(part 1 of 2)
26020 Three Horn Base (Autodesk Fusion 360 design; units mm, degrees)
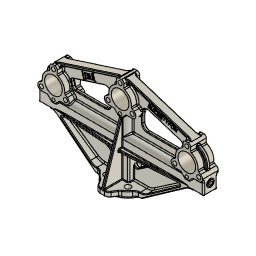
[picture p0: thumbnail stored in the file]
parameter "Bell_Tolerance" = 0.1984 (= "( 1 / 128 ) * 1 in")
parameter "Bolt_Hole_Tolerance" = 0.7937 (= "( 1 / 32 ) * 1 in")
parameter "Dowel_Hole_Tolerance" = 0.0992 (= "( 1 / 256 ) * 1 in")
sketch "Layout Profile" plane through (0, 0, 0) normal (0, 1, 0) x axis (1, 0, 0)
  line L1 (50.8, 0) -> (-50.8, 0)
  line L2 (0, -190.5) -> (0, 0)
  line L3 (168.275, -136.525) -> (-168.275, -136.525)
  line L4 (-110.7733, -12.7) -> (-225.7767, -12.7)
  circle C1 centre (0, -190.5) radius 80.9625
  arc A1 centre (-168.275, -136.525) radius 136.525 clockwise from (-110.7733, -12.7) to (-225.7767, -12.7)
  circle C2 centre (168.275, -136.525) radius 114.3
  point P4 (0, 0)
  point P1 (0, 0)
  point P5 (0, 0)
  point P6 (0, -190.5)
  point P7 (0, -190.5)
  point P10 (0, -136.525)
  point P8 (-168.275, -136.525)
  point P11 (-168.275, -136.525)
  point P9 (168.275, -136.525)
  point P14 (168.275, -136.525)
  point P2 (-50.8, 0)
  point P3 (50.8, 0)
  horizontal L1
  midpoint L1 P4
  coincident P1 P4
  coincident P1 P5
  perpendicular L1 L2
  coincident P6 P7
  horizontal L3
  midpoint L3 P10
  coincident L2 P10
  coincident P8 P11
  horizontal L4
  coincident P9 P14
  dimension "d1" distance P2 P3 = 101.6
  dimension "d2" diameter C1 = 161.925 (= "6 3/8")
  dimension "d3" distance L2 P8 = 168.275 (= "6 5/8")
  dimension "d4" distance L1 L3 = 136.525 (= "5 3/8")
  dimension "d5" distance P7 L3 = 53.975 (= "2 1/8")
  dimension "d6" diameter A1 = 273.05 (= "10 3/4")
  dimension "d7" distance L1 L4 = 12.7 (= "( 1 / 2 ) * 1 in")
  dimension "d8" diameter C2 = 228.6
sketch "Main Profile" plane through (0, 0, 0) normal (0, 1, 0) x axis (1, 0, 0)
  line L1 (50.8, 0) -> (-50.8, 0)
  line L2 (51.5937, -3.175) -> (50.8, 0)
  line L3 (57.15, -3.175) -> (51.5937, -3.175)
  line L4 (168.275, 0) -> (50.8, 0)
  line L5 (168.275, -136.525) -> (168.275, 0)
  line L6 (0, -190.5) -> (0, 0)
  line L7 (64.4424, -15.875) -> (0, -15.875)
  line L8 (157.0466, -79.375) -> (64.4424, -15.875)
  line L9 (168.275, -79.375) -> (57.15, -3.175)
  line L10 (168.275, -180.975) -> (168.275, -136.525)
  line L11 (171.45, -180.975) -> (165.1, -180.975)
  line L12 (177.8, -165.6244) -> (177.8, -174.625)
  line L13 (198.5209, -119.0625) -> (168.275, -136.525)
  line L14 (138.0291, -119.0625) -> (168.275, -136.525)
  line L15 (203.2834, -127.3114) -> (198.2383, -130.2242)
  line L16 (198.5209, -109.5375) -> (183.3562, -109.5375)
  line L17 (172.2438, -98.425) -> (164.3062, -98.425)
  line L18 (183.3562, -109.5375) -> (172.2438, -98.425)
  line L19 (153.1938, -109.5375) -> (164.3062, -98.425)
  line L20 (138.0291, -109.5375) -> (153.1938, -109.5375)
  line L21 (133.2666, -127.3114) -> (138.3117, -130.2242)
  line L22 (158.75, -165.6244) -> (158.75, -174.625)
  line L23 (0, -234.95) -> (0, -190.5)
  line L24 (3.175, -234.95) -> (-3.175, -234.95)
  line L25 (9.525, -219.5994) -> (9.525, -228.6)
  line L26 (30.2459, -163.5125) -> (15.0813, -163.5125)
  line L27 (29.9633, -184.1992) -> (35.0084, -181.2864)
  line L28 (3.9688, -152.4) -> (-3.9687, -152.4)
  line L29 (15.0813, -163.5125) -> (3.9688, -152.4)
  line L30 (-15.0812, -163.5125) -> (-3.9687, -152.4)
  line L31 (-30.2459, -163.5125) -> (-15.0812, -163.5125)
  line L32 (-29.9633, -184.1992) -> (-35.0084, -181.2864)
  line L33 (-9.525, -219.5994) -> (-9.525, -228.6)
  line L34 (-138.0291, -119.0625) -> (-168.275, -136.525)
  line L35 (-138.0291, -109.5375) -> (-153.1938, -109.5375)
  line L36 (-153.1938, -109.5375) -> (-164.3062, -98.425)
  line L37 (-172.2438, -98.425) -> (-164.3062, -98.425)
  line L38 (-183.3562, -109.5375) -> (-172.2438, -98.425)
  line L39 (-198.5209, -109.5375) -> (-183.3562, -109.5375)
  line L40 (-203.2834, -127.3114) -> (-198.2383, -130.2242)
  line L41 (-198.5209, -119.0625) -> (-168.275, -136.525)
  line L42 (-168.275, -180.975) -> (-168.275, -136.525)
  line L43 (-177.8, -165.6244) -> (-177.8, -174.625)
  line L44 (-171.45, -180.975) -> (-165.1, -180.975)
  line L45 (-158.75, -165.6244) -> (-158.75, -174.625)
  line L46 (-133.2666, -127.3114) -> (-138.3117, -130.2242)
  line L47 (-168.275, -136.525) -> (-168.275, 0)
  line L48 (-168.275, 0) -> (-50.8, 0)
  line L49 (173.3895, -180.6716) -> (5.1145, -234.6466)
  line L50 (159.9347, -178.3186) -> (9.525, -226.5632)
  line L51 (135.9945, -159.3229) -> (56.3499, -184.8693)
  line L52 (39.7709, -149.225) -> (39.7709, -172.7761)
  line L53 (52.4709, -136.525) -> (130.7079, -136.525)
  line L54 (130.7079, -136.525) -> (168.275, -136.525)
  line L55 (208.0459, -79.375) -> (208.0459, -119.0625)
  line L56 (0, -79.375) -> (208.0459, -79.375)
  line L57 (128.6373, -117.475) -> (17.4625, -117.475)
  line L58 (168.275, -85.725) -> (168.275, -79.375)
  line L59 (0, -85.725) -> (168.275, -85.725)
  line L60 (17.4625, -163.5125) -> (17.4625, -117.475)
  line L61 (3.175, -49.5697) -> (3.175, -15.875)
  line L62 (3.175, -152.4) -> (3.175, -77.4303)
  line L63 (3.175, -77.4303) -> (3.175, -49.5697)
  line L64 (19.05, -15.875) -> (19.05, -79.375)
  line L65 (14.2875, -79.375) -> (14.2875, -63.5)
  line L66 (61.5498, -67.788) -> (28.9911, -45.462)
  line L67 (-61.5498, -67.788) -> (-28.9911, -45.462)
  line L68 (0, -79.375) -> (-208.0459, -79.375)
  line L69 (-19.05, -15.875) -> (-19.05, -79.375)
  line L70 (-14.2875, -79.375) -> (-14.2875, -63.5)
  line L71 (-3.175, -77.4303) -> (-3.175, -49.5697)
  line L72 (-3.175, -152.4) -> (-3.175, -77.4303)
  line L73 (0, -85.725) -> (-168.275, -85.725)
  line L74 (-3.175, -49.5697) -> (-3.175, -15.875)
  line L75 (-157.0466, -79.375) -> (-64.4424, -15.875)
  line L76 (-64.4424, -15.875) -> (0, -15.875)
  line L77 (-51.5937, -3.175) -> (-50.8, 0)
  line L78 (-57.15, -3.175) -> (-51.5937, -3.175)
  line L79 (-168.275, -79.375) -> (-57.15, -3.175)
  line L80 (-168.275, -85.725) -> (-168.275, -79.375)
  line L81 (-17.4625, -163.5125) -> (-17.4625, -117.475)
  line L82 (-128.6373, -117.475) -> (-17.4625, -117.475)
  line L83 (-39.7709, -149.225) -> (-39.7709, -172.7761)
  line L84 (-135.9945, -159.3229) -> (-56.3499, -184.8693)
  line L85 (-52.4709, -136.525) -> (-130.7079, -136.525)
  line L86 (-130.7079, -136.525) -> (-168.275, -136.525)
  line L87 (-159.9347, -178.3186) -> (-9.525, -226.5632)
  line L88 (-173.3895, -180.6716) -> (-5.1145, -234.6466)
  line L89 (-208.0459, -79.375) -> (-208.0459, -119.0625)
  line L90 (0, -152.4) -> (0, -15.875)
  line L91 (-17.4625, -117.475) -> (17.4625, -117.475)
  line L92 (0, -3.175) -> (51.5937, -3.175)
  line L93 (0, 0) -> (0, -3.175)
  line L94 (-51.5937, -3.175) -> (0, -3.175)
  circle C1 centre (168.275, -136.525) radius 22.3242
  circle C2 centre (0, -190.5) radius 22.3242
  arc A1 centre (171.45, -174.625) radius 6.35 clockwise from (177.8, -174.625) to (171.45, -180.975)
  circle C3 centre (168.275, -171.45) radius 5.1594
  arc A2 centre (180.975, -165.6244) radius 3.175 clockwise from (177.8, -165.6244) to (179.705, -162.7144)
  arc A3 centre (168.275, -136.525) radius 28.575 clockwise from (196.6707, -133.329) to (179.705, -162.7144)
  circle C4 centre (198.5209, -119.0625) radius 5.1594
  circle C5 centre (138.0291, -119.0625) radius 5.1594
  arc A4 centre (199.8258, -132.9738) radius 3.175 clockwise from (196.6707, -133.329) to (198.2383, -130.2242)
  arc A5 centre (198.5209, -119.0625) radius 9.525 clockwise from (198.5209, -109.5375) to (203.2834, -127.3114)
  circle C6 centre (168.275, -104.775) radius 3.9688
  arc A6 centre (138.0291, -119.0625) radius 9.525 clockwise from (133.2666, -127.3114) to (138.0291, -109.5375)
  arc A7 centre (136.7242, -132.9738) radius 3.175 clockwise from (138.3117, -130.2242) to (139.8793, -133.329)
  arc A8 centre (168.275, -136.525) radius 28.575 clockwise from (156.845, -162.7144) to (139.8793, -133.329)
  arc A9 centre (155.575, -165.6244) radius 3.175 clockwise from (156.845, -162.7144) to (158.75, -165.6244)
  arc A10 centre (165.1, -174.625) radius 6.35 clockwise from (165.1, -180.975) to (158.75, -174.625)
  arc A11 centre (3.175, -228.6) radius 6.35 clockwise from (9.525, -228.6) to (3.175, -234.95)
  circle C7 centre (0, -225.425) radius 5.1594
  arc A12 centre (12.7, -219.5994) radius 3.175 clockwise from (9.525, -219.5994) to (11.43, -216.6894)
  arc A13 centre (0, -190.5) radius 28.575 clockwise from (28.3957, -187.304) to (11.43, -216.6894)
  circle C8 centre (30.2459, -173.0375) radius 5.1594
  circle C9 centre (-30.2459, -173.0375) radius 5.1594
  arc A14 centre (30.2459, -173.0375) radius 9.525 clockwise from (30.2459, -163.5125) to (35.0084, -181.2864)
  arc A15 centre (31.5508, -186.9488) radius 3.175 clockwise from (28.3957, -187.304) to (29.9633, -184.1992)
  circle C10 centre (0, -158.75) radius 3.9687
  arc A16 centre (-30.2459, -173.0375) radius 9.525 clockwise from (-35.0084, -181.2864) to (-30.2459, -163.5125)
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  point P4 (0, 0)
  point P1 (0, 0)
  point P8 (168.275, -136.525)
  point P9 (168.275, -136.525)
  point P10 (0, 0)
  point P11 (0, -190.5)
  point P12 (0, -190.5)
  point P15 (0, -190.5)
  point P14 (168.275, -136.525)
  point P16 (0, -15.875)
  point P17 (0, -15.875)
  point P21 (168.275, -136.525)
  point P25 (168.275, -180.975)
  point P22 (168.275, -180.975)
  point P29 (168.275, -171.45)
  point P33 (168.275, -136.525)
  point P36 (168.275, -136.525)
  point P34 (198.5209, -119.0625)
  point P37 (198.5209, -119.0625)
  point P38 (168.275, -136.525)
  point P35 (138.0291, -119.0625)
  point P39 (138.0291, -119.0625)
  point P48 (168.275, -98.425)
  point P49 (168.275, -104.775)
  point P24 (171.45, -180.975)
  point P63 (165.1, -180.975)
  point P26 (177.8, -174.625)
  point P64 (158.75, -174.625)
  point P28 (177.8, -165.6244)
  point P61 (158.75, -165.6244)
  point P30 (179.705, -162.7144)
  point P59 (156.845, -162.7144)
  point P32 (196.6707, -133.329)
  point P57 (139.8793, -133.329)
  point P40 (198.2383, -130.2242)
  point P55 (138.3117, -130.2242)
  point P42 (203.2834, -127.3114)
  point P54 (133.2666, -127.3114)
  point P43 (183.3562, -109.5375)
  point P51 (153.1938, -109.5375)
  point P44 (198.5209, -109.5375)
  point P52 (138.0291, -109.5375)
  point P47 (172.2438, -98.425)
  point P50 (164.3062, -98.425)
  point P69 (0, -234.95)
  point P66 (0, -234.95)
  point P65 (0, -190.5)
  point P73 (0, -225.425)
  point P89 (0, -152.4)
  point P80 (15.0813, -163.5125)
  point P81 (15.0813, -163.5125)
  point P90 (0, -158.75)
  point P68 (3.175, -234.95)
  point P106 (-3.175, -234.95)
  point P70 (9.525, -228.6)
  point P104 (-9.525, -228.6)
  point P72 (9.525, -219.5994)
  point P103 (-9.525, -219.5994)
  point P74 (11.43, -216.6894)
  point P101 (-11.43, -216.6894)
  point P76 (28.3957, -187.304)
  point P99 (-28.3957, -187.304)
  point P92 (-15.0812, -163.5125)
  point P93 (-15.0812, -163.5125)
  point P82 (30.2459, -163.5125)
  point P94 (-30.2459, -163.5125)
  point P83 (35.0084, -181.2864)
  point P96 (-35.0084, -181.2864)
  point P85 (29.9633, -184.1992)
  point P97 (-29.9633, -184.1992)
  point P88 (3.9688, -152.4)
  point P91 (-3.9687, -152.4)
  point P3 (50.8, 0)
  point P151 (-50.8, 0)
  point P7 (168.275, 0)
  point P149 (-168.275, 0)
  point P150 (-168.275, -136.525)
  point P128 (-168.275, -136.525)
  point P129 (-168.275, -180.975)
  point P23 (165.1, -180.975)
  point P135 (-165.1, -180.975)
  point P134 (-171.45, -180.975)
  point P132 (-177.8, -174.625)
  point P131 (-177.8, -165.6244)
  point P124 (-179.705, -162.7144)
  point P122 (-196.6707, -133.329)
  point P126 (-168.275, -136.525)
  point P127 (-198.5209, -119.0625)
  point P108 (-168.275, -136.525)
  point P109 (-138.0291, -119.0625)
  point P120 (-198.2383, -130.2242)
  point P119 (-203.2834, -127.3114)
  point P116 (-183.3562, -109.5375)
  point P117 (-198.5209, -109.5375)
  point P46 (164.3062, -98.425)
  point P114 (-164.3062, -98.425)
  point P115 (-172.2438, -98.425)
  point P113 (-164.3062, -98.425)
  point P111 (-153.1938, -109.5375)
  point P112 (-138.0291, -109.5375)
  point P145 (-133.2666, -127.3114)
  point P146 (-138.3117, -130.2242)
  point P141 (-139.8793, -133.329)
  point P142 (-156.845, -162.7144)
  point P139 (-158.75, -165.6244)
  point P138 (-165.1, -180.975)
  point P137 (-158.75, -174.625)
  point P153 (5.1145, -234.6466)
  point P154 (173.3895, -180.6716)
  point P155 (9.525, -226.5632)
  point P156 (159.9347, -178.3186)
  point P170 (168.275, -136.525)
  point P171 (208.0459, -119.0625)
  point P175 (128.6373, -117.475)
  point P20 (168.275, -79.375)
  point P19 (157.0466, -79.375)
  point P176 (168.275, -79.375)
  point P177 (168.275, -85.725)
  point P178 (0, -85.725)
  point P173 (0, -79.375)
  point P180 (3.175, -15.875)
  point P184 (3.175, -152.4)
  point P183 (0, -63.5)
  point P185 (19.05, -79.375)
  point P186 (19.05, -15.875)
  point P188 (14.2875, -79.375)
  point P190 (20.6375, -117.475)
  point P189 (17.4625, -120.65)
  point P192 (19.05, -50.6991)
  point P196 (57.9586, -79.375)
  point P220 (-50.8, 0)
  point P5 (51.5937, -3.175)
  point P221 (-51.5937, -3.175)
  point P6 (57.15, -3.175)
  point P222 (-57.15, -3.175)
  point P219 (0, -15.875)
  point P18 (64.4424, -15.875)
  point P217 (-64.4424, -15.875)
  point P218 (-157.0466, -79.375)
  point P223 (-168.275, -79.375)
  point P247 (-5.1145, -234.6466)
  point P248 (-173.3895, -180.6716)
  point P245 (-9.525, -226.5632)
  point P246 (-159.9347, -178.3186)
  point P157 (56.3499, -184.8693)
  point P236 (-56.3499, -184.8693)
  point P158 (135.9945, -159.3229)
  point P237 (-135.9945, -159.3229)
  point P159 (39.7709, -172.7761)
  point P234 (-39.7709, -172.7761)
  point P161 (39.7709, -149.225)
  point P233 (-39.7709, -149.225)
  point P162 (139.7584, -150.4844)
  point P240 (-139.7584, -150.4844)
  point P164 (136.9691, -141.8167)
  point P242 (-136.9691, -141.8167)
  point P166 (130.7079, -136.525)
  point P238 (-130.7079, -136.525)
  point P168 (52.4709, -136.525)
  point P232 (-52.4709, -136.525)
  point P244 (-168.275, -136.525)
  point P249 (-208.0459, -119.0625)
  point P172 (208.0459, -79.375)
  point P204 (-208.0459, -79.375)
  point P205 (0, -79.375)
  point P174 (17.4625, -117.475)
  point P225 (-17.4625, -117.475)
  point P230 (-128.6373, -117.475)
  point P224 (-168.275, -79.375)
  point P214 (-168.275, -85.725)
  point P215 (0, -85.725)
  point P179 (17.4625, -163.5125)
  point P226 (-17.4625, -163.5125)
  point P216 (-3.175, -15.875)
  point P181 (3.175, -49.5697)
  point P212 (-3.175, -49.5697)
  point P182 (3.175, -77.4303)
  point P211 (-3.175, -77.4303)
  point P213 (-3.175, -152.4)
  point P206 (-19.05, -79.375)
  point P207 (-19.05, -15.875)
  point P187 (14.2875, -63.5)
  point P208 (-14.2875, -63.5)
  point P209 (-14.2875, -79.375)
  point P229 (-17.4625, -120.65)
  point P228 (-20.6375, -117.475)
  point P200 (-19.05, -50.6991)
  point P193 (28.9911, -45.462)
  point P199 (-28.9911, -45.462)
  point P195 (61.5498, -67.788)
  point P201 (-61.5498, -67.788)
  point P203 (-57.9586, -79.375)
  point P250 (0, -152.4)
  point P254 (177.8, -172.446)
  point P256 (203.9245, -126.9064)
  point P251 (179.9167, -169.4526)
  point P259 (-179.9167, -169.4526)
  point P252 (202.6048, -130.1047)
  point P262 (-202.6048, -130.1047)
  point P260 (-177.8, -172.446)
  point P264 (-203.9245, -126.9064)
  point P265 (0, -3.175)
  point P266 (0, 0)
  point P2 (-50.8, 0)
  point P87 (-3.9687, -152.4)
  point P77 (0, -190.5)
  horizontal L1
  midpoint L1 P4
  coincident P1 P4
  horizontal L3
  parallel L1 L4
  perpendicular L4 L5
  coincident P8 P9
  coincident P1 P10
  perpendicular L1 L6
  coincident P11 P12
  coincident P12 P15
  coincident P9 P14
  coincident L6 P16
  coincident P16 P17
  perpendicular L6 L7
  parallel L8 L9
  coincident P9 P21
  parallel L5 L10
  horizontal L11
  midpoint L11 P25
  coincident P22 P25
  tangent L11 A1
  vertical L12
  tangent A1 L12
  coincident L10 P29
  tangent L12 A2
  tangent A2 A3
  concentric C1 A3
  coincident P33 P36
  coincident P34 P37
  coincident P14 P38
  coincident P35 P39
  tangent A3 A4
  tangent A4 L15
  horizontal L16
  tangent L16 A5
  tangent L15 A5
  concentric C4 A5
  perpendicular L5 L17
  midpoint L17 P48
  coincident L5 P48
  coincident L5 P49
  symmetric L10 P24 P63
  symmetric L10 P26 P64
  symmetric L10 A1 A10
  symmetric L10 P28 P61
  symmetric L10 P30 P59
  symmetric L10 A2 A9
  symmetric L10 P32 P57
  symmetric L10 A3 A8
  symmetric L10 P40 P55
  symmetric L10 A4 A7
  symmetric L10 P42 P54
  symmetric L10 P43 P51
  symmetric L10 P44 P52
  symmetric L10 A5 A6
  symmetric L10 P47 P50
  parallel L6 L23
  horizontal L24
  midpoint L24 P69
  coincident P66 P69
  coincident P15 P65
  tangent L24 A11
  tangent A11 L25
  vertical L25
  coincident L23 P73
  tangent L25 A12
  tangent A12 A13
  concentric C2 A13
  tangent L26 A14
  concentric C8 A14
  tangent A14 L27
  tangent L27 A15
  tangent A13 A15
  perpendicular L6 L28
  midpoint L28 P89
  coincident L6 P89
  coincident P80 P81
  horizontal L26
  coincident L6 P90
  symmetric L23 P68 P106
  symmetric L23 P70 P104
  symmetric L23 P72 P103
  symmetric L23 P74 P101
  symmetric L23 P76 P99
  symmetric L23 P80 P92
  symmetric L23 P81 P93
  symmetric L23 P82 P94
  symmetric L23 P83 P96
  symmetric L23 A14 A16
  symmetric L23 P85 P97
  symmetric L23 P88 P91
  symmetric P3 L6 P151
  symmetric P7 L6 P149
  symmetric P8 L6 P150
  symmetric L6 P21 P128
  symmetric L6 P22 P129
  symmetric L6 P23 P135
  symmetric L6 P24 P134
  symmetric L6 P26 P132
  symmetric L6 P28 P131
  symmetric L6 P30 P124
  symmetric L6 P32 P122
  symmetric L6 P36 P126
  symmetric L6 P37 P127
  symmetric L6 P38 P108
  symmetric L6 P39 P109
  symmetric L6 P40 P120
  symmetric L6 P42 P119
  symmetric L6 P43 P116
  symmetric L6 P44 P117
  symmetric L6 P46 P114
  symmetric L6 P47 P115
  symmetric L6 P50 P113
  symmetric L6 P51 P111
  symmetric L6 P52 P112
  symmetric L6 P54 P145
  symmetric L6 P55 P146
  symmetric L6 P57 P141
  symmetric L6 P59 P142
  symmetric L6 P61 P139
  symmetric L6 P63 P138
  symmetric L6 P64 P137
  coincident A11 P153
  tangent A11 L49
  coincident A1 P154
  tangent A1 L49
  parallel L49 L50
  coincident L25 P155
  coincident A10 P156
  parallel L50 L51
  vertical L52
  tangent A14 L52
  horizontal L53
  coincident P14 P170
  horizontal L54
  coincident A5 P171
  vertical L55
  tangent A5 L55
  perpendicular L55 L56
  horizontal L57
  coincident A6 P175
  coincident P20 L56
  coincident L5 P20
  coincident P19 L56
  coincident L5 P176
  coincident L56 P176
  coincident L5 P177
  perpendicular L56 L58
  perpendicular L5 L59
  perpendicular L57 L60
  coincident L6 P178
  coincident L6 P173
  coincident L7 P180
  perpendicular L7 L61
  perpendicular L57 L62
  coincident L28 P184
  coincident L6 P183
  parallel L62 L63
  coincident L56 P185
  coincident L7 P186
  perpendicular L7 L64
  coincident L56 P188
  perpendicular L56 L65
  coincident L57 P190
  coincident L60 P189
  coincident L64 P192
  coincident L56 P196
  parallel L8 L66
  symmetric P3 L6 P220
  symmetric P5 L6 P221
  symmetric P6 L6 P222
  symmetric L6 P17 P219
  symmetric L6 P18 P217
  symmetric L6 P19 P218
  symmetric L6 P20 P223
  symmetric L6 P153 P247
  symmetric L6 P154 P248
  symmetric L6 P155 P245
  symmetric L6 P156 P246
  symmetric L6 P157 P236
  symmetric L6 P158 P237
  symmetric L6 P159 P234
  symmetric L6 P161 P233
  symmetric L6 P162 P240
  symmetric L6 P164 P242
  symmetric L6 P166 P238
  symmetric L6 P168 P232
  symmetric L6 P170 P244
  symmetric L6 P171 P249
  symmetric L6 P172 P204
  symmetric L6 P173 P205
  symmetric L6 P174 P225
  symmetric L6 P175 P230
  symmetric L6 P176 P224
  symmetric L6 P177 P214
  symmetric L6 P178 P215
  symmetric L6 P179 P226
  symmetric L6 P180 P216
  symmetric L6 P181 P212
  symmetric L6 P182 P211
  symmetric L6 P184 P213
  symmetric L6 P185 P206
  symmetric L6 P186 P207
  symmetric L6 P187 P208
  symmetric L6 P188 P209
  symmetric L6 P189 P229
  symmetric L6 P190 P228
  symmetric L6 P192 P200
  symmetric L6 P193 P199
  symmetric L6 P195 P201
  symmetric L6 P196 P203
  coincident P89 P250
  coincident L12 P254
  coincident A5 P256
  symmetric L90 P251 P259
  symmetric L90 P252 P262
  symmetric L90 P254 P260
  symmetric L90 P256 P264
  coincident L6 P265
  perpendicular L6 L92
  coincident P4 P266
  coincident L26 P179
  dimension "d9" distance P2 P3 = 101.6
  dimension "d10" distance P3 P5 = 0.7937 (= "( 1 / 32 ) * 1 in")
  dimension "d11" diameter C1 = 44.6484 (= "1 3/4  + Bell_Tolerance")
  dimension "d12" distance L3 L4 = 3.175 (= "( 1 / 8 ) * 1 in")
  dimension "d13" diameter C2 = 44.6484 (= "1 3/4  + Bell_Tolerance")
  dimension "d18" distance L1 L7 = 15.875 (= "( 5 / 8 ) * 1 in")
  dimension "d19" distance L8 L9 = 6.35 (= "( 1 / 4 ) * 1 in")
  dimension "d20" distance P3 P6 = 6.35 (= "( 1 / 4 ) * 1 in")
  dimension "d24" radius A1 = 6.35 (= "( 1 / 4 ) * 1 in")
  dimension "d25" distance P9 L11 = 44.45 (= "1 3/4")
  dimension "d26" diameter C3 = 10.3188 (= "( 3 / 8 ) * 1 in + Bolt_Hole_Tolerance")
  dimension "d27" distance L10 L12 = 9.525 (= "( 3 / 8 ) * 1 in")
  dimension "d28" distance P9 P29 = 34.925 (= "1 3/8")
  dimension "d29" radius A2 = 3.175 (= "( 1 / 8 ) * 1 in")
  dimension "d30" radius A3 = 28.575 (= "1 1/8")
  dimension "d33" radius A4 = 3.175 (= "( 1 / 8 ) * 1 in")
  dimension "d34" radius A5 = 9.525 (= "( 3 / 8 ) * 1 in")
  dimension "d35" angle L15 L16 = 30
  dimension "d36" angle L16 L18 = 135
  dimension "d37" distance P38 L17 = 38.1 (= "1 1/2")
  dimension "d38" diameter C6 = 7.9375 (= "( 5 / 16 ) * 1 in")
  dimension "d39" distance P9 P49 = 31.75 (= "1 1/4")
  dimension "d40" distance P46 P47 = 7.9375 (= "( 5 / 16 ) * 1 in")
  dimension "d41" distance P12 L24 = 44.45 (= "1 3/4")
  dimension "d42" radius A11 = 6.35 (= "( 1 / 4 ) * 1 in")
  dimension "d43" diameter C7 = 10.3188 (= "( 3 / 8 ) * 1 in + Bolt_Hole_Tolerance")
  dimension "d44" distance P12 P73 = 34.925 (= "1 3/8")
  dimension "d45" distance L23 L25 = 9.525 (= "( 3 / 8 ) * 1 in")
  dimension "d46" radius A12 = 3.175 (= "( 1 / 8 ) * 1 in")
  dimension "d47" radius A13 = 28.575 (= "1 1/8")
  dimension "d50" radius A14 = 9.525 (= "( 3 / 8 ) * 1 in")
  dimension "d52" angle L26 L27 = 30
  dimension "d53" radius A15 = 3.175 (= "( 1 / 8 ) * 1 in")
  dimension "d54" distance P87 P88 = 7.9375 (= "( 5 / 16 ) * 1 in")
  dimension "d55" angle L26 L29 = 135
  dimension "d56" distance P77 L28 = 38.1 (= "1 1/2")
  dimension "d57" diameter C10 = 7.9375 (= "( 5 / 16 ) * 1 in")
  dimension "d58" distance P77 P90 = 31.75 (= "1 1/4")
  dimension "d59" distance L49 L50 = 6.35 (= "( 1 / 4 ) * 1 in")
  dimension "d60" distance L49 L51 = 31.75 (= "1 1/4")
  dimension "d61" radius = 12.7 (= "( 1 / 2 ) * 1 in")
  dimension "d62" radius = 6.35 (= "( 1 / 4 ) * 1 in")
  dimension "d63" distance = 3.175 (= "( 1 / 8 ) * 1 in")
  dimension "d64" radius = 6.35 (= "( 1 / 4 ) * 1 in")
  dimension "d65" radius = 12.7 (= "( 1 / 2 ) * 1 in")
  dimension "d66" distance L53 L57 = 19.05 (= "( 3 / 4 ) * 1 in")
  dimension "d67" distance L56 L57 = 38.1 (= "1 1/2")
  dimension "d68" distance L56 L59 = 6.35 (= "( 1 / 4 ) * 1 in")
  dimension "d69" distance L6 L60 = 17.4625
  dimension "d70" distance L6 L61 = 3.175 (= "( 1 / 8 ) * 1 in")
  dimension "d71" distance L1 P183 = 63.5 (= "2 1/2")
  dimension "d72" radius = 14.2875
  dimension "d73" distance L6 L64 = 19.05
  dimension "d74" radius = 3.175 (= "( 1 / 8 ) * 1 in")
  dimension "d75" distance L8 L66 = 44.45 (= "1 3/4")
  dimension "d76" radius = 6.35 (= "( 1 / 4 ) * 1 in")
  dimension "d77" radius = 6.35 (= "( 1 / 4 ) * 1 in")
  dimension "d87" distance = 6.35 (= "( 1 / 4 ) * 1 in")
  dimension "d88" radius = 3.175 (= "( 1 / 8 ) * 1 in")
  dimension "d89" radius = 3.175 (= "( 1 / 8 ) * 1 in")
  dimension "d32" C-Pattern1-Angle = 360
  dimension "d49" C-Pattern2-Angle = 360
extrude "Extrude1" new body sketch "Main Profile" profile of L11 A1 A10 A11 L25 L28 L49 L50 L56 L58 L59 L62 L68 L72 L73 distance 20.6375 (= "( 13 / 16 ) * 1 in")
extrude "Extrude2" add sketch "Main Profile" distance 39.6875 (= "1 9/16")
extrude "Extrude3" add sketch "Main Profile" distance 34.925 (= "1 3/8")
revolve "Revolve1" sketch "Main Profile" AlongAngle 360
delete_face "DeleteFace1"
extrude "Extrude4" add sketch "Main Profile" distance 7.9375 (= "( 5 / 16 ) * 1 in")
extrude "Extrude5" add sketch "Main Profile" profile of L3 L7 L8 L9 L56 L68 L75 L76 L78 L79 L92 L94 distance 130.175 (= "5 1/8")
revolve "Revolve2" sketch "Main Profile" AlongAngle 360
sketch "Bottom Profile" plane through (0, 0, 0) normal (0, 0, -1) x axis (1, 0, 0)
  line L1 (0, 38.1) -> (0, 0)
  line L2 (26.9408, 26.9408) -> (0, 0)
  line L3 (0, 65.0875) -> (0, 38.1)
  line L4 (12.7, 65.0875) -> (-12.7, 65.0875)
  line L5 (25.4, 44.9083) -> (12.7, 65.0875)
  line L6 (168.275, 17.4625) -> (44.9083, 25.4)
  line L7 (168.275, 17.4625) -> (168.275, 65.0875)
  line L8 (168.275, 65.0875) -> (57.15, 65.0875)
  line L9 (57.15, 65.0875) -> (-57.15, 65.0875)
  line L10 (221.5629, 0) -> (0, 0)
  line L11 (25.4, -44.9083) -> (12.7, -65.0875)
  line L12 (168.275, -17.4625) -> (44.9083, -25.4)
  line L13 (12.7, -65.0875) -> (-12.7, -65.0875)
  line L14 (168.275, -17.4625) -> (168.275, 17.4625)
  line L15 (-168.275, 17.4625) -> (-44.9083, 25.4)
  line L16 (-168.275, -17.4625) -> (-44.9083, -25.4)
  line L17 (-221.5629, 0) -> (0, 0)
  line L18 (-25.4, -44.9083) -> (-12.7, -65.0875)
  line L19 (-25.4, 44.9083) -> (-12.7, 65.0875)
  line L20 (-168.275, -17.4625) -> (-168.275, 17.4625)
  line L21 (-168.275, 17.4625) -> (-168.275, 65.0875)
  line L22 (-168.275, 65.0875) -> (-57.15, 65.0875)
  line L23 (168.275, -65.0875) -> (57.15, -65.0875)
  line L24 (168.275, -17.4625) -> (168.275, -65.0875)
  line L25 (57.15, -65.0875) -> (-57.15, -65.0875)
  line L26 (-168.275, -65.0875) -> (-57.15, -65.0875)
  line L27 (-168.275, -17.4625) -> (-168.275, -65.0875)
  circle C1 centre (0, 0) radius 50.8
  circle C2 centre (0, 0) radius 38.1
  circle C3 centre (26.9408, 26.9408) radius 7.1437
  circle C4 centre (-26.9408, 26.9408) radius 7.1437
  circle C5 centre (-26.9408, -26.9408) radius 7.1437
  circle C6 centre (26.9408, -26.9408) radius 7.1437
  circle C7 centre (0, 0) radius 50.8
  circle C8 centre (0, 0) radius 51.5937
  circle C9 centre (0, 0) radius 50.8
  circle C10 centre (0, 0) radius 51.5937
  point P1 (0, 0)
  point P3 (0, 0)
  point P4 (0, 0)
  point P5 (0, 38.1)
  point P6 (0, 0)
  point P7 (26.9408, 26.9408)
  point P8 (26.9408, 26.9408)
  point P15 (0, 65.0875)
  point P12 (0, 65.0875)
  point P19 (25.4, 44.9083)
  point P20 (44.9083, 25.4)
  point P21 (168.275, 17.4625)
  point P23 (168.275, 17.4625)
  point P17 (0, 0)
  point P26 (0, 0)
  point P13 (-12.7, 65.0875)
  point P32 (-12.7, -65.0875)
  point P14 (12.7, 65.0875)
  point P28 (12.7, -65.0875)
  point P29 (25.4, -44.9083)
  point P30 (44.9083, -25.4)
  point P31 (168.275, -17.4625)
  point P41 (-12.7, 65.0875)
  point P42 (-25.4, 44.9083)
  point P33 (-44.9083, 25.4)
  point P34 (-168.275, 17.4625)
  point P37 (0, 0)
  point P27 (221.5629, 0)
  point P38 (-221.5629, 0)
  point P39 (-12.7, -65.0875)
  point P40 (-25.4, -44.9083)
  point P35 (-44.9083, -25.4)
  point P36 (-168.275, -17.4625)
  point P43 (-168.275, 17.4625)
  point P22 (168.275, 65.0875)
  point P45 (-168.275, 65.0875)
  point P46 (-168.275, 17.4625)
  point P24 (57.15, 65.0875)
  point P47 (-57.15, 65.0875)
  point P44 (-168.275, -17.4625)
  point P49 (168.275, -65.0875)
  point P50 (168.275, -17.4625)
  point P48 (57.15, -65.0875)
  point P25 (-57.15, 65.0875)
  point P51 (-57.15, -65.0875)
  point P53 (-168.275, -65.0875)
  point P54 (-168.275, -17.4625)
  point P52 (-57.15, -65.0875)
  coincident P1 P3
  coincident P3 P4
  coincident C2 P5
  vertical L1
  coincident P1 P6
  coincident C2 P7
  coincident P7 P8
  parallel L1 L3
  horizontal L4
  midpoint L4 P15
  coincident P12 P15
  coincident C10 P19
  coincident C8 P20
  coincident P21 L7
  coincident P21 P23
  coincident P17 P26
  perpendicular L1 L10
  symmetric P13 L10 P32
  symmetric P14 L10 P28
  symmetric P19 L10 P29
  symmetric P20 L10 P30
  symmetric P21 L10 P31
  symmetric L1 P14 P41
  symmetric L1 P19 P42
  symmetric L1 P20 P33
  symmetric L1 P21 P34
  symmetric L1 P26 P37
  symmetric L1 P27 P38
  symmetric L1 P28 P39
  symmetric L1 P29 P40
  symmetric L1 P30 P35
  symmetric L1 P31 P36
  symmetric L1 P21 P43
  symmetric L1 P22 P45
  symmetric L1 P23 P46
  symmetric L1 P24 P47
  symmetric L1 P31 P44
  symmetric P22 L10 P49
  symmetric P23 L10 P50
  symmetric P24 L10 P48
  symmetric P25 L10 P51
  symmetric L10 P45 P53
  symmetric L10 P46 P54
  symmetric L10 P47 P52
  dimension "d93" angle L1 L2 = 45
  dimension "d94" diameter C3 = 14.2875 (= "( 9 / 16 ) * 1 in")
  dimension "d97" diameter C2 = 76.2
  dimension "d98" distance P3 L4 = 65.0875 (= "2 9/16")
  dimension "d99" distance P13 P14 = 25.4
  dimension "d100" distance L3 P19 = 25.4
  dimension "d101" distance P1 P20 = 25.4
  dimension "d96" C-Pattern1-Angle = 360
extrude "Extrude6" cut sketch "Bottom Profile" profile of C8 C10 L5 L6 L7 L8 L9 L11 L12 L15 L16 L18 L19 L21 L22 L23 L24 L25 L26 L27 against normal blind 88.9
extrude "Extrude7" cut sketch "Bottom Profile" profile of C3 C4 C5 C6 against normal blind 15.875
sketch "Web Profile 1" plane through (0, 0, 79.375) normal (0, 0, 1) x axis (-1, 0, 0)
  line L1 (-168.275, 17.4625) -> (-157.0466, 18.1849)
  line L2 (-157.0466, 17.4625) -> (-168.275, 17.4625)
  line L3 (-157.0466, 18.1849) -> (-157.0466, 17.4625)
  line L4 (-20.235, 26.9875) -> (-168.275, 17.4625)
  line L5 (0, 26.9875) -> (-20.235, 26.9875)
  line L6 (0, 0) -> (0, 26.9875)
  line L7 (-157.0466, 18.1849) -> (-64.4424, 24.1432)
  line L8 (-168.275, 0) -> (0, 0)
  line L9 (-168.275, 17.4625) -> (-168.275, 0)
  point P3 (-168.275, 17.4625)
  point P5 (-168.275, 17.4625)
  point P1 (0, 0)
  point P8 (0, 0)
  point P11 (0, 0)
  point P13 (-168.275, 17.4625)
  point P14 (0, 17.4625)
  coincident P3 P5
  parallel L2 L5
  coincident P1 P8
  vertical L6
  parallel L4 L7
  coincident P1 P11
  perpendicular L6 L8
  coincident P3 P13
  vertical L9
  dimension "d110" distance L5 P14 = 9.525 (= "( 3 / 8 ) * 1 in")
extrude "Extrude8" add sketch "Web Profile 1" along normal blind 6.35 (= "( 1 / 4 ) * 1 in")
split "Split1"
remove_body "RemoveBody1"
remove_body "RemoveBody2"
split "Split2"
remove_body "RemoveBody3"
fillet "Fillet1" radius 12.7 (= "( 1 / 2 ) * 1 in")
fillet "Fillet2" radius 31.75 (= "1 1/4")
fillet "Fillet3" radius 11.1125
extrude "Extrude9" add of existing geometry blind 0.762
fillet "Fillet5" radius 13.4938 (= "( 17 / 32 ) * 1 in")
fillet "Fillet6" radius 3.175 (= "( 1 / 8 ) * 1 in")
fillet "Fillet4" radius 3.175 (= "( 1 / 8 ) * 1 in")
fillet "Fillet7" radius 1.5875 (= "( 1 / 16 ) * 1 in")
fillet "Fillet8" radius 3.175 (= "( 1 / 8 ) * 1 in")
fillet "Fillet9" radius 2.3812
fillet "Fillet10" radius 3.175 (= "( 1 / 8 ) * 1 in")
fillet "Fillet11" radius 1.5875 (= "( 1 / 16 ) * 1 in")
fillet "Fillet12" radius 3.175 (= "( 1 / 8 ) * 1 in")
fillet "Fillet13" radius 25.4
fillet "Fillet14" radius 1.5875 (= "( 1 / 16 ) * 1 in")
mirror "Mirror1" mirrorStitchTolerance 0.1016
extrude "Extrude10" add sketch "Main Profile" along normal blind 38.1 (= "1 1/2")
sketch "Web Profile 2" plane through (0, 0, 0) normal (1, 0, 0) x axis (0, 1, 0)
  line L1 (17.4625, 77.7875) -> (0, 77.7875)
  line L2 (17.4625, 49.2125) -> (17.4625, 77.7875)
  line L3 (0, 49.2125) -> (17.4625, 49.2125)
  line L4 (0, 77.7875) -> (0, 49.2125)
  line L5 (38.1, 77.7875) -> (38.1, 49.2125)
  line L6 (0, 77.7875) -> (17.4625, 77.7875)
  line L7 (0, 49.2125) -> (0, 77.7875)
  line L8 (17.4625, 49.2125) -> (0, 49.2125)
  line L9 (17.4625, 17.4625) -> (17.4625, 49.2125)
  line L10 (63.5, 15.875) -> (19.05, 15.875)
  line L11 (65.0875, 4.7625) -> (65.0875, 14.2875)
  line L12 (51.5937, 3.175) -> (63.5, 3.175)
  line L13 (50.8, 0) -> (51.5937, 3.175)
  line L14 (-50.8, 0) -> (50.8, 0)
  line L15 (-51.5937, 3.175) -> (-50.8, 0)
  line L16 (-63.5, 3.175) -> (-51.5937, 3.175)
  line L17 (-65.0875, 14.2875) -> (-65.0875, 4.7625)
  line L18 (-19.05, 15.875) -> (-63.5, 15.875)
  line L19 (-17.4625, 79.375) -> (-17.4625, 17.4625)
  line L20 (-25.4, 79.375) -> (-17.4625, 79.375)
  line L21 (-26.9875, 84.1375) -> (-26.9875, 80.9625)
  line L22 (-17.4625, 85.725) -> (-25.4, 85.725)
  line L23 (-17.4625, 103.9813) -> (-17.4625, 85.725)
  line L24 (-17.4625, 150.0188) -> (-17.4625, 103.9813)
  line L25 (-19.8438, 154.7813) -> (-19.8438, 152.4)
  line L26 (19.8438, 154.7813) -> (-19.8438, 154.7813)
  line L27 (19.8438, 152.4) -> (19.8438, 154.7813)
  line L28 (19.8437, 152.4) -> (19.8438, 152.4)
  line L29 (17.4625, 103.9813) -> (17.4625, 150.0188)
  line L30 (17.4625, 85.725) -> (17.4625, 103.9813)
  line L31 (25.4, 85.725) -> (17.4625, 85.725)
  line L32 (26.9875, 80.9625) -> (26.9875, 84.1375)
  line L33 (17.4625, 79.375) -> (25.4, 79.375)
  line L34 (17.4625, 77.7875) -> (17.4625, 79.375)
  line L35 (36.5125, 49.2125) -> (64.7204, 15.3027)
  line L36 (17.4625, 49.2125) -> (38.1, 49.2125)
  line L37 (19.05, 152.2638) -> (36.5125, 77.7875)
  line L38 (-65.0056, 14.7908) -> (-19.05, 152.2638)
  line L39 (17.4625, 77.7875) -> (38.1, 77.7875)
  arc A1 centre (19.05, 17.4625) radius 1.5875 clockwise from (19.05, 15.875) to (17.4625, 17.4625)
  arc A2 centre (63.5, 14.2875) radius 1.5875 clockwise from (63.5, 15.875) to (65.0875, 14.2875)
  arc A3 centre (63.5, 4.7625) radius 1.5875 clockwise from (65.0875, 4.7625) to (63.5, 3.175)
  arc A4 centre (-63.5, 4.7625) radius 1.5875 clockwise from (-63.5, 3.175) to (-65.0875, 4.7625)
  arc A5 centre (-63.5, 14.2875) radius 1.5875 clockwise from (-65.0875, 14.2875) to (-63.5, 15.875)
  arc A6 centre (-19.05, 17.4625) radius 1.5875 clockwise from (-17.4625, 17.4625) to (-19.05, 15.875)
  arc A7 centre (-25.4, 80.9625) radius 1.5875 clockwise from (-25.4, 79.375) to (-26.9875, 80.9625)
  arc A8 centre (-25.4, 84.1375) radius 1.5875 clockwise from (-26.9875, 84.1375) to (-25.4, 85.725)
  arc A9 centre (-19.8437, 150.0188) radius 2.3812 clockwise from (-19.8438, 152.4) to (-17.4625, 150.0188)
  arc A10 centre (19.8437, 150.0188) radius 2.3812 clockwise from (17.4625, 150.0188) to (19.8437, 152.4)
  arc A11 centre (25.4, 84.1375) radius 1.5875 clockwise from (25.4, 85.725) to (26.9875, 84.1375)
  arc A12 centre (25.4, 80.9625) radius 1.5875 clockwise from (26.9875, 80.9625) to (25.4, 79.375)
  point P61 (64.7204, 15.3027)
  point P6 (38.1, 49.2125)
  point P63 (38.1, 49.2125)
  point P4 (17.4625, 49.2125)
  point P64 (17.4625, 49.2125)
  point P69 (-65.0056, 14.7908)
  point P62 (36.5125, 49.2125)
  point P7 (38.1, 77.7875)
  point P70 (38.1, 77.7875)
  point P3 (17.4625, 77.7875)
  point P71 (17.4625, 77.7875)
  point P65 (36.5125, 77.7875)
  point P66 (19.05, 152.2638)
  point P72 (19.8437, 152.4)
  point P68 (-19.05, 152.2638)
  point P45 (-19.8438, 152.4)
  point P67 (-19.8438, 152.4)
  coincident A2 P61
  tangent A2 L35
  coincident P6 P63
  coincident P4 P64
  coincident A5 P69
  tangent A5 L38
  coincident P62 L36
  coincident P7 P70
  coincident P3 P71
  coincident P65 L39
  coincident A10 P66
  coincident A10 P72
  coincident A9 P68
  coincident P45 P67
  dimension "d169" distance P62 P63 = 1.5875 (= "( 1 / 16 ) * 1 in")
  dimension "d170" distance P7 P65 = 1.5875 (= "( 1 / 16 ) * 1 in")
  dimension "d179" distance P66 P72 = 0.7937 (= "( 1 / 32 ) * 1 in")
  dimension "d180" distance P67 P68 = 0.7937 (= "( 1 / 32 ) * 1 in")
extrude "Extrude11" add sketch "Web Profile 2" profile of L9 A1 L10 A2 A5 L18 A6 L19 L20 A7 L21 A8 L22 L23 L24 A9 A10 L29 L30 L31 A11 L32 A12 L33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 along normal blind 3.175 (= "( 1 / 8 ) * 1 in")
delete_face "DeleteFace3"
delete_face "DeleteFace4"
delete_face "DeleteFace5"
fillet "Fillet15" radius 1.5875 (= "( 1 / 16 ) * 1 in")
extrude "Extrude12" add sketch "Main Profile" along normal blind 26.9875
extrude "Extrude13" add of existing geometry blind 2.032
delete_face "DeleteFace2"
fillet "Fillet23" radius 0.7937 (= "( 1 / 32 ) * 1 in")
fillet "Fillet24" radius 1.5875 (= "( 1 / 16 ) * 1 in")
fillet "Fillet25" radius 0.7937 (= "( 1 / 32 ) * 1 in")
fillet "Fillet26" radius 1.5875 (= "( 1 / 16 ) * 1 in")
fillet "Fillet27" radius 0.3969 (= "( 1 / 64 ) * 1 in")
split "Split4"
remove_body "RemoveBody5"
mirror "Mirror3" mirrorStitchTolerance 0.1016
fillet "Fillet28" radius 1.5875 (= "( 1 / 16 ) * 1 in")
sketch "Piping Profile 1" plane through (208.0459, 0, 0) normal (1, 0, 0) x axis (0, 1, 0)
  line L1 (14.2875, 82.55) -> (-14.2875, 82.55)
  line L2 (14.2875, 108.991) -> (14.2875, 82.55)
  curve K1 (19.8437, 119.0625) -> (14.2875, 108.991)
  line L3 (-19.8437, 119.0625) -> (19.8437, 119.0625)
  curve K2 (-19.8437, 119.0625) -> (-14.2875, 108.991)
  line L4 (-14.2875, 82.55) -> (-14.2875, 108.991)
  line L5 (-14.2875, 82.55) -> (14.2875, 82.55)
  line L6 (-14.2875, 82.55) -> (-14.2875, 79.375)
  line L7 (14.2875, 79.375) -> (-14.2875, 79.375)
  line L8 (14.2875, 82.55) -> (14.2875, 79.375)
  line L9 (-14.2875, 82.55) -> (-14.2875, 79.375)
  line L10 (-17.4625, 82.55) -> (-14.2875, 82.55)
  line L11 (-14.2875, 108.991) -> (-17.4625, 108.991)
  line L12 (-17.4625, 82.55) -> (-17.4625, 108.991)
  line L13 (-17.4625, 82.55) -> (-14.2875, 82.55)
  line L14 (-14.2875, 108.991) -> (-14.2875, 82.55)
  line L15 (14.2875, 108.991) -> (17.4625, 108.991)
  line L16 (14.2875, 82.55) -> (14.2875, 108.991)
  line L17 (17.4625, 82.55) -> (14.2875, 82.55)
  line L18 (17.4625, 108.991) -> (17.4625, 82.55)
  line L19 (17.4625, 82.55) -> (14.2875, 82.55)
  line L20 (14.2875, 82.55) -> (14.2875, 79.375)
  line L21 (0, 119.0625) -> (0, 79.375)
  arc A1 centre (-14.2875, 82.55) radius 3.175 clockwise from (-14.2875, 79.375) to (-17.4625, 82.55)
  arc A2 centre (14.2875, 82.55) radius 3.175 clockwise from (17.4625, 82.55) to (14.2875, 79.375)
  circle C1 centre (0, 101.6) radius 7.1437
  point P26 (0, 79.375)
  point P27 (0, 119.0625)
  point P28 (0, 101.6)
  midpoint L7 P26
  midpoint L3 P27
  coincident L21 P28
  dimension "d187" diameter C1 = 14.2875 (= "( 9 / 16 ) * 1 in")
  dimension "d188" distance L7 P28 = 22.225 (= "( 7 / 8 ) * 1 in")
offset_faces "OffsetFaces1"
extrude "Extrude14" cut sketch "Piping Profile 1" profile of C1 against normal blind 416.1028
sketch "Piping Profile 2" plane through (0, 0, 0) normal (0, 0, -1) x axis (1, 0, 0)
  circle C1 centre (-26.9408, 26.9408) radius 7.1437
  circle C2 centre (-26.9408, -26.9408) radius 7.1437
  circle C3 centre (26.9408, -26.9408) radius 7.1437
  circle C4 centre (0, 0) radius 50.8
  circle C5 centre (26.9408, 26.9408) radius 7.1437
  circle C6 centre (0, 0) radius 9.1281
  circle C7 centre (0, 0) radius 7.1437
  point P1 (0, 0)
  point P7 (0, 0)
  coincident P1 P7
  concentric C6 C7
  dimension "d192" diameter C6 = 18.2563
  dimension "d193" diameter C7 = 14.2875 (= "( 9 / 16 ) * 1 in")
extrude "Extrude15" cut sketch "Piping Profile 2" profile of C7 against normal blind 158.75
extrude "Extrude16" cut sketch "Piping Profile 2" profile of C6 C7 against normal blind 19.05 (magnitude of "( -3 / 4 ) * 1 in")
chamfer "Chamfer1" distance 0.3969 (= "( 1 / 64 ) * 1 in")
sketch "Main Profile" plane through (0, 0, 0) normal (0, 1, 0) x axis (1, 0, 0)
  line L1 (208.0459, -108.991) -> (208.0459, -82.55)
  line L2 (209.6334, -101.6) -> (208.0459, -101.6)
  line L3 (204.8709, -79.375) -> (176.1471, -79.375)
  line L4 (204.8709, -101.6) -> (208.0459, -101.6)
  line L5 (209.6334, -104.9766) -> (209.6334, -101.6)
  line L6 (208.0459, -111.125) -> (208.0459, -108.991)
  line L7 (204.8709, -101.6) -> (204.8709, -108.7438)
  line L8 (208.0459, -108.7438) -> (204.8709, -108.7438)
  arc A1 centre (214.3959, -111.125) radius 6.35 clockwise from (208.0459, -111.125) to (208.8397, -108.0508)
  arc A2 centre (203.2834, -104.9766) radius 6.35 clockwise from (209.6334, -104.9766) to (208.8397, -108.0508)
  point P4 (208.0459, -101.6)
  point P3 (208.0459, -108.991)
  point P10 (208.0459, -108.991)
  point P16 (208.0459, -108.7438)
  point P8 (204.8709, -101.6)
  point P5 (209.6334, -101.6)
  point P11 (208.0459, -111.125)
  coincident L1 P4
  perpendicular L1 L2
  perpendicular L1 L4
  vertical L5
  coincident P3 P10
  parallel L1 L6
  tangent L6 A1
  tangent L5 A2
  tangent A1 A2
  vertical L7
  coincident L1 P16
  perpendicular L1 L8
  dimension "d199" distance L2 L3 = 22.225 (= "( 7 / 8 ) * 1 in")
  dimension "d200" distance P4 P8 = 3.175 (= "( 1 / 8 ) * 1 in")
  dimension "d201" distance P4 P5 = 1.5875 (= "( 1 / 16 ) * 1 in")
  dimension "d202" radius A1 = 6.35 (= "( 1 / 4 ) * 1 in")
  dimension "d203" radius A2 = 6.35 (= "d202")
  dimension "d204" distance L2 P11 = 9.525 (= "( 3 / 8 ) * 1 in")
  dimension "d206" distance L4 L8 = 7.1437 (= "( 9 / 32 ) * 1 in")
revolve "Revolve1" sketch "Main Profile" AlongAngle 360 bodies "Plug Weld"
copy_paste "CopyPaste1"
